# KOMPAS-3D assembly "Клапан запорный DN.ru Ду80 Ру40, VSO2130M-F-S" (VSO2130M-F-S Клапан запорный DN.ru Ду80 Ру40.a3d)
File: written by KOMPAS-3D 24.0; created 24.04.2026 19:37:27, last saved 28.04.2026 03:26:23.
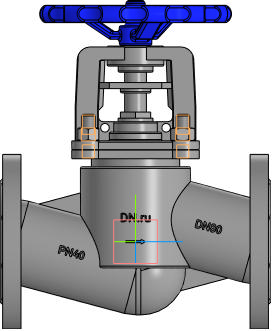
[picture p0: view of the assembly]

Document properties: Автор: DN.ru; Полное имя файла: C:\Работа\ГОТОВЫЕ ИСХОДНИКИ\VSO2130M-F-S Клапан запорный сильфонный DN.ru Ду15-100 Ру40\исходные материалы\DN80\VSO2130M-F-S Клапан запорный DN.ru Ду80 Ру40.a3d

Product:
- Component [detail]: Корпус  | qty 1  | pos. 1  | Масса: 6.9; Автор: R2D2; source file: Korpus.m3d
- Component [detail]: Деталь  | qty 1  | pos. 2  | Масса: 5.908059; Автор: mrdid; source file: rama.m3d
- Component [detail]: Деталь2  | qty 1  | pos. 3  | Масса: 2.292394; Автор: R2D2; additional columns: Типовые; source file: shturval.m3d
- Component [standard]: Шпилька М16-6gx35 ГОСТ 22032-76  | qty 4  | Масса: 0.07017; Раздел спецификации: Стандартные изделия; Рассекать на разрезах: no
- Component [standard]: Гайка М16-6H ГОСТ 5915-70  | qty 4  | Масса: 0.03761; Раздел спецификации: Стандартные изделия; Рассекать на разрезах: no
- Part/product: Клапан запорный DN.ru Ду80 Ру40  | designation VSO2130M-F-S
    Масса: 22
    Раздел спецификации: Прочие изделия
    Примечание: D090-01977

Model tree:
1. Контекстная связь:1  (with: Эскиз:2, Ребро.Элемент выдавливания:14, Контекстная связь (Деталь):1)
2. Контекстная связь:2  (with: Контекстная связь (Деталь):2)
3. Массив по концентрической сетке:1  (with: Грань.Элемент выдавливания:1, Грань.Элемент выдавливания:15, Грань.Элемент выдавливания:3, Грань.Элемент выдавливания:2, Грань.Элемент выдавливания:16, Грань.Элемент выдавливания:17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)  (labels: Грань.Твердое тело1)  (4 pattern instances)
     Шаг 2 = 360; Угол = 8

Referenced files in C:\Работа\ГОТОВЫЕ ИСХОДНИКИ\VSO2130M-F-S Клапан запорный сильфонный DN.ru Ду15-100 Ру40\исходные материалы\DN80\: Korpus.m3d, rama.m3d, shturval.m3d
Referenced files in C:\Program Files\ASCON\KOMPAS-3D v24\Libs\PolynomLib\DATA\vault\Methods\Kompas\3D\: PLib_Stud_1_900.m3d, PLib_Nut_OST92_900.m3d
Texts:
  Крепежное изделие ГОСТ
  BOSimple***PART:d7cea355-acbb-e7a9-246f-9517ee95b2f8***SHORTLOC:Root±30±20±10±120±10±20[Нет;Без покрытия;Без указания материала;-;16;35;2;2]
  BOSimple***PART:17b45fe1-43c8-f41a-5df4-ae57481e6c3b***SHORTLOC:Root±30±10±20±©{}110±10±50±60[Нет;Без покрытия;Без указания материала;-;16;2;24]
  Программные изделия  и базы данных
  VSO2130M-F-S
  Деталь2 Деталь2
  Шпилька М16-6gx35 ГОСТ 22032-76 (1)
  cut1
  bcut1
  hole1
  hcut1
  hole2
  Плоскость XY.Начало координат
  Plane. Начало координат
